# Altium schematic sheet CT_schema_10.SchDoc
size 147 x 119 mm
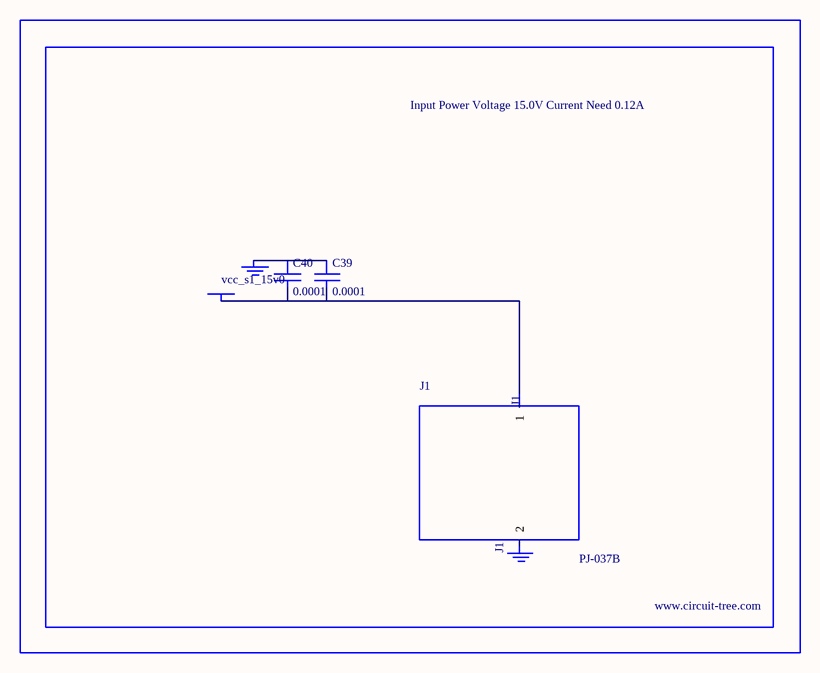
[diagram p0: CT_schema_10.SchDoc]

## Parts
BORDER9  (no value)
C39  0.0001  [EXV-9H]
C40  0.0001  [EXV-9H]
GND_INSTANCE_9_0  (no value)
GND_INSTANCE_9_1  (no value)
J1  PJ-037B  [PJ-037B_PACKAGE]
POWER_INSTANCE_9_0  vcc_s1_15v0

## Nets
NetC39_1: C39.1 C40.1 GND_INSTANCE_9_0.0(GND)
NetC39_2: C39.2 C40.2 J1.1 POWER_INSTANCE_9_0.0(PWR)

Not connected (* = marked no-connect by the designer): GND_INSTANCE_9_1 0(GND); J1 2

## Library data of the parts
BORDER9 = BORDER_PAGE9
C39 C40 = EDK107M035A9HAA
GND_INSTANCE_9_0 GND_INSTANCE_9_1 = GND
POWER_INSTANCE_9_0 = PWR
